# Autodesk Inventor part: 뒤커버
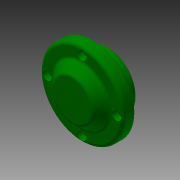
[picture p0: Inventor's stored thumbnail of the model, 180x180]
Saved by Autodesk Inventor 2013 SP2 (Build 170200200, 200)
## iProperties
Created: 2017-08
Part Number: 뒤커버
Material: 알루미늄 6061
Document SubType Name: Modeling
Designer: mduedu
Density: 2.71 g/cm^3
Author: mduedu
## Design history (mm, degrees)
sketch "스케치1"
  geometry: C1 r 35 at (0, 0); 1 further point
  constraints: 1 centre point, 1 coincident
  dimensions: "d0" = 70 diameter of C1
extrude "돌출1" new body sketch "스케치1" distance "d1" = 10; taper "d2" = 0 deg
sketch "스케치2"
  geometry: C1 r 24 at (0, 0); 1 further point
  constraints: 1 centre point, 1 coincident
  dimensions: "d3" = 48 diameter of C1
node "작업 평면1"
sketch "스케치3"
  geometry: C1 r 17 at (0, 0); 1 further point
  constraints: 1 centre point, 1 coincident
  dimensions: "d5" = 34 diameter of C1
feature "로프트1" sketch "스케치3" dims "d6" = 0, "d7" = 90 deg, "d8" = 0, "d9" = 90 deg
sketch "스케치4"
  geometry: C1 r 24 at (0, 0) reference; 1 further point
extrude "돌출2" join sketch "스케치4" distance "d10" = 12; taper "d11" = 0 deg
hole "구멍1" diameter "d14" = 40; stored, may be unused: countersink angle "d18" = 90 deg, drill point angle "d20" = 0 deg; dims "d15" = 6, "d16" = 4, "d17" = 2, "d19" = 12, "d64" = 10, "d65" = 10
hole "구멍2" diameter "d23" = 36; stored, may be unused: countersink angle "d27" = 90 deg, drill point angle "d29" = 0 deg; dims "d24" = 6, "d25" = 4, "d26" = 2, "d28" = 8, "d62" = 10, "d63" = 10
chamfer "모따기1" distance "d39" = 1; stored, may be unused: second distance "d40" = 2, angle "d41" = 45 deg
fillet "모깎기1" dims "d42" = 0.3
fillet "모깎기2" dims "d43" = 3
sketch "스케치5" dims "d44" = 58
  geometry: 6 further points
  constraints: 2 vertical alignment, 1 coincident, 7 other
  dimensions: "d47" = 360 deg dimension on point (0, 0) point (0, 29) (derived)
sketch "스케치6"
  geometry: 4 further points
  constraints: 4 other
hole "구멍4" sketch "스케치6" at (0, 29), (-29, 0), (29, 0), (0, -29) diameter "d49" = 4.5; stored, may be unused: countersink angle "d53" = 90 deg, drill point angle "d55" = 0 deg; dims "d50" = 6, "d51" = 8, "d52" = 4.6, "d54" = 8
fillet "모깎기3" dims "d56" = 3
fillet "모깎기4" dims "d57" = 3
fillet "모깎기5" dims "d58" = 3
chamfer "모따기2" distance "d59" = 1; stored, may be unused: second distance "d60" = 2, angle "d61" = 45 deg
node "솔리드1"
other parameters: "d4" = 8
